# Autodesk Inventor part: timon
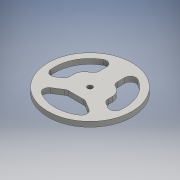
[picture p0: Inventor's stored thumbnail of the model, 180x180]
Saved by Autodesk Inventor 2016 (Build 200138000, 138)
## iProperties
Created: 2017-06
Part Number: timon
Material: Generic
Document SubType Name: Modeling
Designer: laboratorioesan
Density: 1 g/cm^3
Appearance: Default
Author: laboratorioesan
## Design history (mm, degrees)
sketch "Sketch1"
  geometry: L1 (-70, 50)-(70, 50); L2 (70, 50)-(70, -50); L3 (70, -50)-(-70, -50); L4 (-70, -50)-(-70, 50); L5 (-33.1, 50)-(-33.1, 123.129); L6 (33.1, 50)-(33.1, 123.129); L7 (-118.763, -46.385)-(-70, -15.436); L8 (70, -15.436)-(118.763, -46.385); L9 (33.1, -50)-(92.529, -87.719); L10 (-92.529, -87.719)-(-33.1, -50); C1 r 140 at (0, 0); C2 r 152.5 at (0, 0); C3 r 9 at (0, 0); A1 r 127.5 centre (0, 0) between (92.529, -87.719) and (118.763, -46.385); 3 further points
  constraints: 20 end point, 6 point on circle, 6 point on line, 4 centre point, 4 coincident, 4 parallel, 3 vertical alignment, 2 horizontal alignment, 2 midpoint, 2 perpendicular, 1 horizontal
  dimensions: "d0" = 280 diameter of C1; "d1" = 140 distance of L1.start L1.end; "d2" = 100 distance of L1.end L2.end; "d3" = 255 diameter of A1; "d4" = 305 diameter of C2; "d5" = 18 diameter of C3
extrude "Extrusion1" new body sketch "Sketch1" distance "d6" = 18.5; taper "d7" = 0 deg
fillet "Fillet1" dims "d8" = 40
fillet "Fillet2" dims "d9" = 20
fillet "Fillet3" dims "d10" = 20
body "Solid1"
